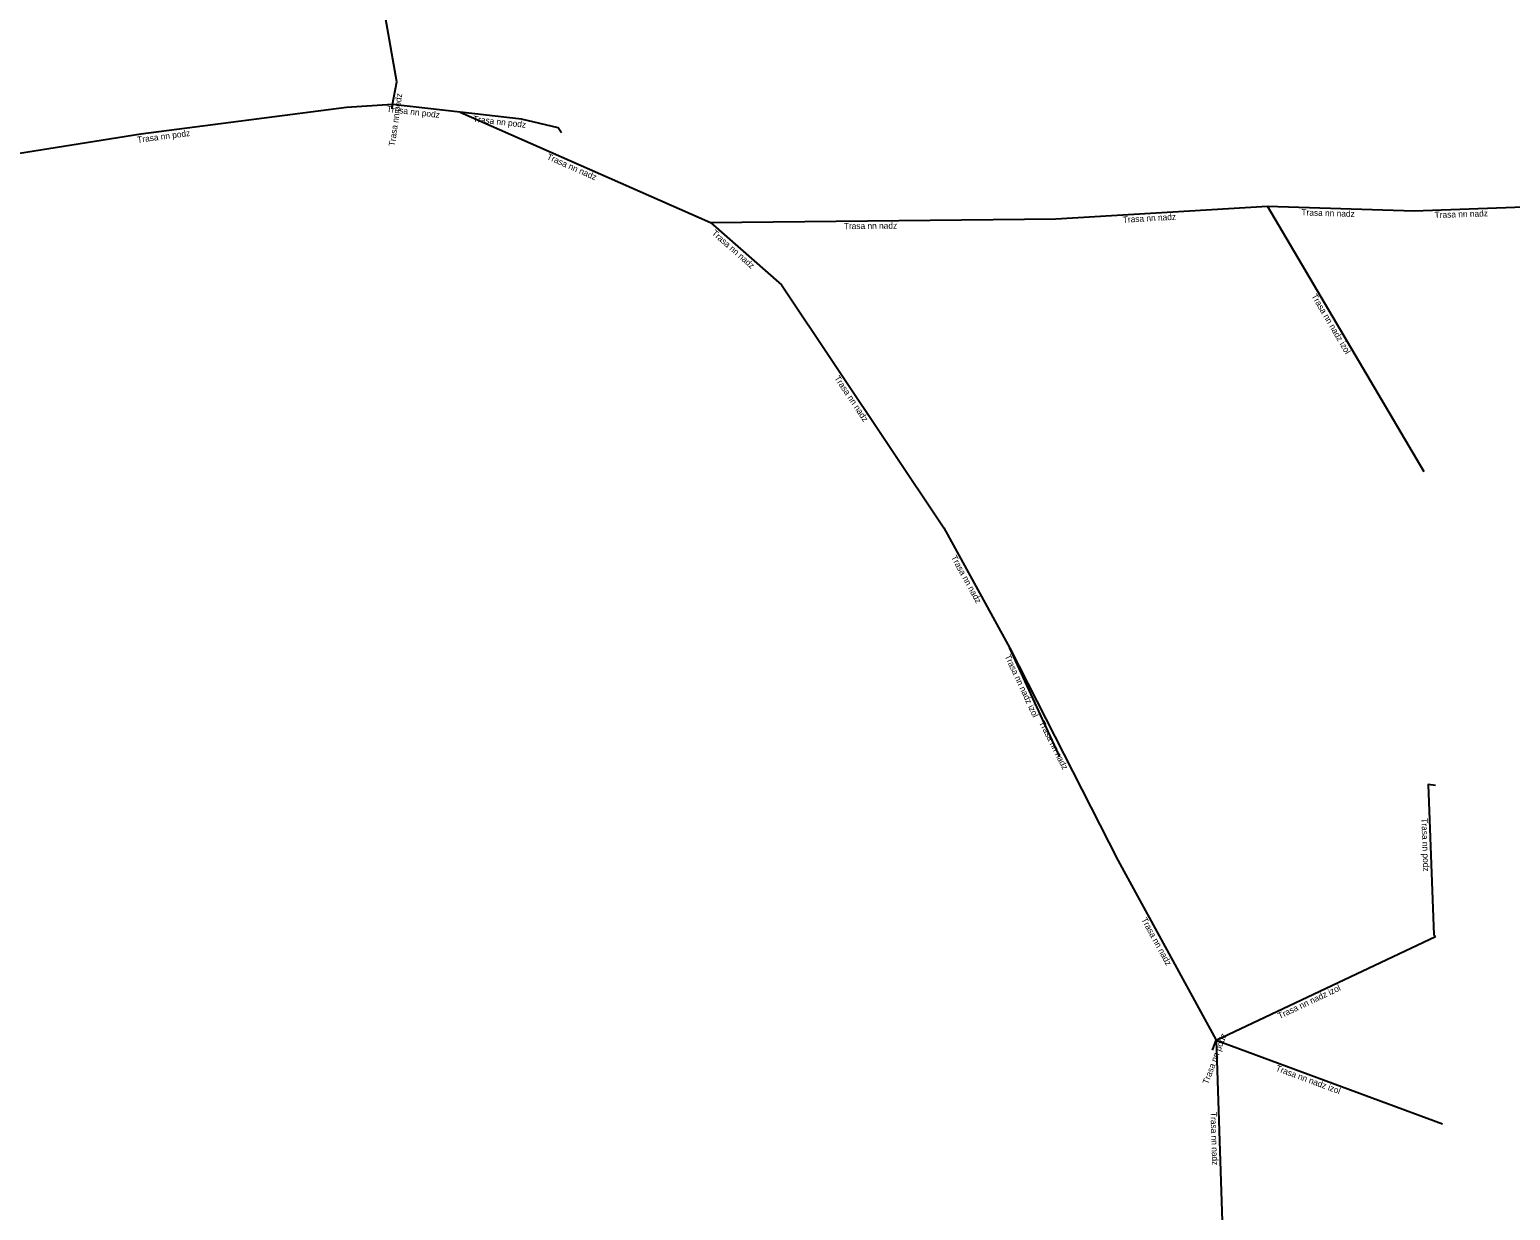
# Model space of a CAD drawing. Extents: x -682739 to -681564, y -1060091 to -1059590.
# Drawn here: x -682002.1 to -681883.4, y -1059838.9 to -1059744.3 of the extents above; entities that cross this region are included whole.
import ezdxf

# ---------------------------------------------------------------- set-up
doc = ezdxf.new("R2010")
doc.units = 0
doc.layers.add('Popiskový text - Ostatní atributy Trasy', color=7, linetype='Continuous')
doc.layers.add('Spojnice NN', color=7, linetype='Continuous')

msp = doc.modelspace()

# ---------------------------------------------------------------- linework, layer by layer
at = {"layer": 'Spojnice NN'}
for points in [[(-681973.04, -1059750.26), (-681972.7, -1059748.45), (-681974.51, -1059738.12), (-681975.24, -1059732.95), (-681972.09, -1059716.76), (-681971.62, -1059716.28), (-681969.28, -1059716.84)], [(-681973.04, -1059750.26), (-681976.75, -1059750.5), (-681993.23, -1059752.66), (-682006.15, -1059754.71), (-682006.44, -1059755.34), (-682006.62, -1059755.81), (-682006.45, -1059756.21)], [(-681973.09, -1059750.61), (-681973.04, -1059750.26)], [(-681967.62, -1059750.89), (-681973.04, -1059750.26)], [(-681959.5, -1059752.55), (-681959.77, -1059752.14), (-681962.7, -1059751.45), (-681967.62, -1059750.89)], [(-681967.62, -1059750.89), (-681947.56, -1059759.74)], [(-681919.89, -1059759.43), (-681902.91, -1059758.43)], [(-681902.91, -1059758.43), (-681891.16, -1059758.79)], [(-681890.35, -1059779.73), (-681902.91, -1059758.43)], [(-681891.16, -1059758.79), (-681881.62, -1059758.46)], [(-681947.56, -1059759.74), (-681919.89, -1059759.43)], [(-681947.56, -1059759.74), (-681941.87, -1059764.74)], [(-681941.87, -1059764.74), (-681928.86, -1059784.2)], [(-681928.86, -1059784.2), (-681923.58, -1059793.85)], [(-681923.58, -1059793.85), (-681914.91, -1059810.86)], [(-681919.55, -1059802.57), (-681923.58, -1059793.85)], [(-681889.45, -1059804.86), (-681890.03, -1059804.79), (-681889.59, -1059816.83), (-681889.45, -1059816.98)], [(-681914.91, -1059810.86), (-681907.04, -1059825.29)], [(-681907.04, -1059825.29), (-681889.45, -1059816.98)], [(-681907.33, -1059826.08), (-681907.04, -1059825.29)], [(-681907.04, -1059825.29), (-681906.43, -1059843.05)], [(-681907.04, -1059825.29), (-681888.88, -1059831.99)]]:
    msp.add_lwpolyline(points, dxfattribs=at)

# ---------------------------------------------------------------- texts
at = {"layer": 'Popiskový text - Ostatní atributy Trasy'}
for s, rotation, p in [('Trasa nn podz', 81.8699, (-681972.87, -1059753.64)), ('Trasa nn podz', 353.3699, (-681973.53, -1059750.86)), ('Trasa nn podz', 353.5065, (-681966.62, -1059751.66)), ('Trasa nn podz', 7.4671, (-681993.48, -1059753.35)), ('Trasa nn nadz', 336.1941, (-681960.73, -1059754.64)), ('Trasa nn nadz', 3.3704, (-681914.5, -1059759.76)), ('Trasa nn nadz', 358.2602, (-681900.2, -1059759.16)), ('Trasa nn nadz', 1.9573, (-681889.51, -1059759.38)), ('Trasa nn nadz', 318.6788, (-681947.51, -1059760.65)), ('Trasa nn nadz', 0.6419, (-681936.87, -1059760.27)), ('Trasa nn nadz izol', 300.5283, (-681899.42, -1059765.63)), ('Trasa nn nadz', 303.7756, (-681937.66, -1059772.21)), ('Trasa nn nadz', 298.6907, (-681928.3, -1059786.57)), ('Trasa nn nadz izol', 294.7785, (-681923.99, -1059794.5)), ('Trasa nn nadz', 297.0066, (-681921.25, -1059799.84)), ('Trasa nn podz', 272.06, (-681890.58, -1059807.5)), ('Trasa nn nadz', 298.5996, (-681913.05, -1059815.62)), ('Trasa nn nadz izol', 25.2967, (-681901.94, -1059823.6)), ('Trasa nn podz', 69.6199, (-681907.67, -1059828.86)), ('Trasa nn nadz izol', 339.7428, (-681902.3, -1059827.73)), ('Trasa nn nadz', 271.9605, (-681907.49, -1059831.05))]:
    msp.add_text(s, height=0.5, rotation=rotation, dxfattribs=at).set_placement(p)

doc.saveas('drawing.dxf')
